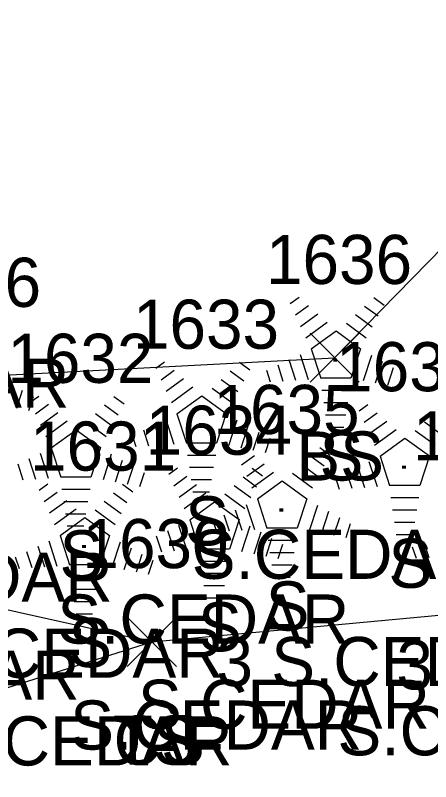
# Model space of a CAD drawing. Extents: x 1499292 to 1501024, y 534584 to 538043.
# Drawn here: x 1499918.42 to 1499935.33, y 537630.3 to 537661.49 of the extents above; entities that cross this region are included whole.
import ezdxf

# ---------------------------------------------------------------- set-up
doc = ezdxf.new("R2010")
doc.units = 0
for name, color, linetype in [('L_A', 7, 'Continuous'), ('L_C', 7, 'Continuous'), ('L_I', 7, 'Continuous'), ('L_TIC', 7, 'Continuous'), ('LELB', 7, 'Continuous'), ('LTC', 7, 'Continuous')]:
    doc.layers.add(name, color=color, linetype=linetype)

msp = doc.modelspace()

# ---------------------------------------------------------------- linework, layer by layer
at = {"layer": 'L_TIC'}
for points in [[(1499930.422, 537646.554), (1499932.422, 537648.554)], [(1499932.422, 537646.554), (1499930.422, 537648.554)], [(1499922.982, 537634.989), (1499924.982, 537636.989)], [(1499924.982, 537634.989), (1499922.982, 537636.989)], [(1499922.982, 537634.989), (1499924.982, 537636.989)], [(1499924.982, 537634.989), (1499922.982, 537636.989)]]:
    msp.add_lwpolyline(points, dxfattribs=at)
at = {"layer": 'LELB'}
for points in [[(1499846.934, 537679.187), (1499854.63, 537681.892), (1499855.345, 537682.192), (1499861.643, 537684.623), (1499869.851, 537675.621), (1499886.591, 537651.746), (1499898.304, 537639.55), (1499906.005, 537630.298), (1499923.982, 537635.989)], [(1499898.052, 537654.523), (1499915.347, 537646.709), (1499931.422, 537647.554), (1499937.751, 537654.019), (1499948.365, 537655.7)], [(1499898.052, 537654.523), (1499910.254, 537639.037), (1499923.982, 537635.989), (1499941.209, 537637.588), (1499959.262, 537638.094), (1499978.567, 537642.414), (1499993.025, 537642.588)]]:
    msp.add_lwpolyline(points, dxfattribs=at)
at = {"layer": 'LTC'}
for p, q in [((1499929.617, 537649.762), (1499929.972, 537650.02)), ((1499933.015, 537650.002), (1499933.434, 537649.698)), ((1499929.827, 537649.297), (1499930.356, 537649.681)), ((1499932.644, 537649.654), (1499933.194, 537649.255)), ((1499930.036, 537648.831), (1499930.74, 537649.342)), ((1499932.273, 537649.306), (1499932.952, 537648.812)), ((1499930.246, 537648.365), (1499931.124, 537649.003)), ((1499931.902, 537648.957), (1499932.712, 537648.369)), ((1499930.47, 537647.91), (1499931.482, 537648.645)), ((1499931.482, 537648.645), (1499932.479, 537647.92)), ((1499930.47, 537647.91), (1499930.857, 537646.717)), ((1499932.479, 537647.92), (1499932.088, 537646.717)), ((1499929.56, 537647.475), (1499929.832, 537646.639)), ((1499930.016, 537647.691), (1499930.347, 537646.672)), ((1499932.917, 537647.649), (1499932.579, 537646.609)), ((1499933.361, 537647.398), (1499933.074, 537646.514)), ((1499924.147, 537647.125), (1499924.501, 537647.383)), ((1499927.545, 537647.366), (1499927.964, 537647.061)), ((1499929.105, 537647.258), (1499929.317, 537646.606)), ((1499933.806, 537647.148), (1499933.569, 537646.419)), ((1499924.356, 537646.66), (1499924.886, 537647.044)), ((1499927.174, 537647.017), (1499927.723, 537646.618)), ((1499928.649, 537647.041), (1499928.802, 537646.573)), ((1499934.25, 537646.898), (1499934.063, 537646.324)), ((1499924.566, 537646.194), (1499925.27, 537646.705)), ((1499926.803, 537646.669), (1499927.482, 537646.175)), ((1499932.088, 537646.717), (1499930.857, 537646.717)), ((1499918.701, 537646.218), (1499918.464, 537645.488)), ((1499924.776, 537645.728), (1499925.654, 537646.366)), ((1499926.432, 537646.321), (1499927.241, 537645.732)), ((1499932.049, 537646.217), (1499930.905, 537646.217)), ((1499919.145, 537645.967), (1499918.959, 537645.393)), ((1499919.03, 537645.738), (1499919.385, 537645.995)), ((1499922.429, 537645.978), (1499922.848, 537645.674)), ((1499925, 537645.273), (1499926.012, 537646.008)), ((1499926.012, 537646.008), (1499927.009, 537645.283)), ((1499919.24, 537645.272), (1499919.769, 537645.657)), ((1499922.057, 537645.63), (1499922.607, 537645.231)), ((1499931.966, 537645.717), (1499930.977, 537645.717)), ((1499932.421, 537645.397), (1499932.775, 537645.654)), ((1499919.45, 537644.807), (1499920.153, 537645.318)), ((1499921.687, 537645.282), (1499922.366, 537644.788)), ((1499925, 537645.273), (1499925.387, 537644.08)), ((1499927.009, 537645.283), (1499926.618, 537644.08)), ((1499931.882, 537645.217), (1499931.05, 537645.217)), ((1499932.63, 537644.931), (1499933.16, 537645.316)), ((1499919.659, 537644.341), (1499920.537, 537644.979)), ((1499921.315, 537644.933), (1499922.125, 537644.345)), ((1499924.546, 537645.054), (1499924.876, 537644.035)), ((1499927.446, 537645.012), (1499927.108, 537643.972)), ((1499932.84, 537644.466), (1499933.544, 537644.977)), ((1499935.077, 537644.941), (1499935.756, 537644.447)), ((1499919.884, 537643.886), (1499920.895, 537644.62)), ((1499920.895, 537644.62), (1499921.892, 537643.895)), ((1499923.635, 537644.621), (1499923.846, 537643.969)), ((1499924.09, 537644.838), (1499924.361, 537644.002)), ((1499927.891, 537644.762), (1499927.603, 537643.877)), ((1499931.798, 537644.717), (1499931.123, 537644.717)), ((1499933.05, 537644), (1499933.928, 537644.638)), ((1499934.706, 537644.592), (1499935.515, 537644.004)), ((1499923.179, 537644.404), (1499923.331, 537643.937)), ((1499928.336, 537644.512), (1499928.098, 537643.782)), ((1499933.274, 537643.545), (1499934.286, 537644.279)), ((1499934.286, 537644.279), (1499935.283, 537643.554)), ((1499926.618, 537644.08), (1499925.387, 537644.08)), ((1499928.78, 537644.261), (1499928.593, 537643.687)), ((1499919.429, 537643.667), (1499919.76, 537642.647)), ((1499919.884, 537643.886), (1499920.271, 537642.692)), ((1499921.892, 537643.895), (1499921.501, 537642.692)), ((1499927.426, 537643.657), (1499927.78, 537643.914)), ((1499930.824, 537643.897), (1499931.243, 537643.593)), ((1499918.974, 537643.45), (1499919.245, 537642.615)), ((1499922.33, 537643.625), (1499921.992, 537642.585)), ((1499922.775, 537643.374), (1499922.487, 537642.49)), ((1499926.579, 537643.58), (1499925.435, 537643.58)), ((1499927.635, 537643.191), (1499928.164, 537643.576)), ((1499930.453, 537643.549), (1499931.002, 537643.15)), ((1499933.274, 537643.545), (1499933.661, 537642.351)), ((1499935.283, 537643.554), (1499934.892, 537642.351)), ((1499918.518, 537643.234), (1499918.73, 537642.582)), ((1499923.219, 537643.124), (1499922.982, 537642.395)), ((1499924.669, 537642.812), (1499925.024, 537643.069)), ((1499926.496, 537643.08), (1499925.507, 537643.08)), ((1499927.845, 537642.726), (1499928.548, 537643.237)), ((1499928.068, 537643.052), (1499928.487, 537642.748)), ((1499930.082, 537643.201), (1499930.761, 537642.707)), ((1499932.364, 537643.109), (1499932.635, 537642.274)), ((1499932.82, 537643.326), (1499933.15, 537642.306)), ((1499923.663, 537642.874), (1499923.477, 537642.3)), ((1499924.879, 537642.346), (1499925.408, 537642.73)), ((1499928.054, 537642.26), (1499928.933, 537642.898)), ((1499929.711, 537642.852), (1499930.52, 537642.263)), ((1499931.909, 537642.893), (1499932.12, 537642.241)), ((1499919.39, 537642.165), (1499919.744, 537642.423)), ((1499921.501, 537642.692), (1499920.271, 537642.692)), ((1499922.788, 537642.406), (1499923.207, 537642.101)), ((1499926.412, 537642.58), (1499925.58, 537642.58)), ((1499927.696, 537642.704), (1499928.246, 537642.305)), ((1499928.279, 537641.805), (1499929.291, 537642.539)), ((1499929.291, 537642.539), (1499930.288, 537641.814)), ((1499931.453, 537642.676), (1499931.605, 537642.208)), ((1499921.463, 537642.192), (1499920.318, 537642.192)), ((1499925.088, 537641.88), (1499925.792, 537642.392)), ((1499927.326, 537642.355), (1499928.005, 537641.862)), ((1499934.892, 537642.351), (1499933.661, 537642.351)), ((1499919.599, 537641.7), (1499920.129, 537642.084)), ((1499922.417, 537642.057), (1499922.966, 537641.658)), ((1499925.298, 537641.415), (1499926.176, 537642.053)), ((1499926.328, 537642.08), (1499925.653, 537642.08)), ((1499926.954, 537642.007), (1499927.764, 537641.418)), ((1499928.279, 537641.805), (1499928.666, 537640.611)), ((1499930.288, 537641.814), (1499929.896, 537640.611)), ((1499934.853, 537641.851), (1499933.709, 537641.851)), ((1499919.809, 537641.234), (1499920.513, 537641.745)), ((1499921.379, 537641.692), (1499920.391, 537641.692)), ((1499922.046, 537641.709), (1499922.725, 537641.215)), ((1499925.523, 537640.96), (1499926.534, 537641.694)), ((1499926.534, 537641.694), (1499927.531, 537640.969)), ((1499927.824, 537641.586), (1499928.155, 537640.566)), ((1499930.725, 537641.543), (1499930.387, 537640.504)), ((1499920.019, 537640.768), (1499920.897, 537641.406)), ((1499921.295, 537641.192), (1499920.464, 537641.192)), ((1499921.675, 537641.361), (1499922.484, 537640.772)), ((1499927.369, 537641.369), (1499927.64, 537640.534)), ((1499931.17, 537641.293), (1499930.882, 537640.408)), ((1499934.77, 537641.351), (1499933.781, 537641.351)), ((1499920.243, 537640.313), (1499921.255, 537641.048)), ((1499921.255, 537641.048), (1499922.252, 537640.323)), ((1499925.523, 537640.96), (1499925.91, 537639.766)), ((1499926.458, 537640.936), (1499926.61, 537640.468)), ((1499926.913, 537641.153), (1499927.125, 537640.501)), ((1499927.531, 537640.969), (1499927.14, 537639.766)), ((1499931.614, 537641.043), (1499931.377, 537640.313)), ((1499934.686, 537640.851), (1499933.854, 537640.851)), ((1499921.212, 537640.692), (1499920.537, 537640.692)), ((1499925.068, 537640.74), (1499925.399, 537639.721)), ((1499927.969, 537640.698), (1499927.631, 537639.659)), ((1499929.896, 537640.611), (1499928.666, 537640.611)), ((1499932.058, 537640.793), (1499931.872, 537640.218)), ((1499920.243, 537640.313), (1499920.63, 537639.12)), ((1499922.252, 537640.323), (1499921.861, 537639.12)), ((1499924.157, 537640.308), (1499924.369, 537639.656)), ((1499924.613, 537640.524), (1499924.884, 537639.689)), ((1499928.413, 537640.448), (1499928.126, 537639.563)), ((1499934.602, 537640.351), (1499933.927, 537640.351)), ((1499919.789, 537640.094), (1499920.119, 537639.075)), ((1499922.689, 537640.052), (1499922.351, 537639.012)), ((1499923.702, 537640.091), (1499923.854, 537639.623)), ((1499928.858, 537640.198), (1499928.621, 537639.468)), ((1499929.858, 537640.111), (1499928.713, 537640.111)), ((1499929.302, 537639.948), (1499929.116, 537639.373)), ((1499935.039, 537640.075), (1499935.251, 537639.424)), ((1499918.878, 537639.661), (1499919.089, 537639.009)), ((1499919.333, 537639.878), (1499919.604, 537639.042)), ((1499923.134, 537639.801), (1499922.846, 537638.917)), ((1499927.14, 537639.766), (1499925.91, 537639.766)), ((1499929.774, 537639.611), (1499928.786, 537639.611)), ((1499934.584, 537639.859), (1499934.736, 537639.391)), ((1499918.422, 537639.444), (1499918.574, 537638.976)), ((1499923.579, 537639.551), (1499923.341, 537638.822)), ((1499924.023, 537639.301), (1499923.836, 537638.727)), ((1499921.861, 537639.12), (1499920.63, 537639.12)), ((1499927.102, 537639.266), (1499925.957, 537639.266)), ((1499929.691, 537639.111), (1499928.859, 537639.111)), ((1499927.018, 537638.766), (1499926.03, 537638.766)), ((1499921.822, 537638.62), (1499920.678, 537638.62)), ((1499929.607, 537638.611), (1499928.932, 537638.611)), ((1499921.739, 537638.12), (1499920.75, 537638.12)), ((1499926.934, 537638.266), (1499926.103, 537638.266)), ((1499926.851, 537637.766), (1499926.176, 537637.766)), ((1499921.655, 537637.62), (1499920.823, 537637.62)), ((1499921.571, 537637.12), (1499920.896, 537637.12))]:
    msp.add_line(p, q, dxfattribs=at)

# ---------------------------------------------------------------- texts
at = {"layer": 'L_A'}
for s, p in [('BS', (1499929.863, 537642.554)), ('S', (1499930.808, 537642.554)), ('S', (1499925.337, 537639.917)), ('S', (1499920.221, 537638.53)), ('S', (1499933.611, 537638.189)), ('S', (1499928.616, 537636.449)), ('S', (1499925.86, 537635.604)), ('S', (1499920.58, 537634.957)), ('TS', (1499922.391, 537630.989)), ('CS', (1499922.423, 537630.989))]:
    msp.add_text(s, height=2, dxfattribs=at).set_placement(p)
at = {"layer": 'L_C'}
for s, p in [('S.CEDAR', (1499908.735, 537645.517)), ('S.CEDAR', (1499925.603, 537638.554)), ('S.CEDAR', (1499910.498, 537637.623)), ('S.CEDAR', (1499920.133, 537635.917)), ('S.CEDAR', (1499915.016, 537634.53)), ('3 S.CEDAR', (1499926.611, 537634.189)), ('3 S.CEDAR', (1499933.939, 537634.053)), ('S.CEDAR', (1499909.15, 537633.635)), ('S.CEDAR', (1499923.412, 537632.449)), ('S.CEDAR', (1499920.655, 537631.604)), ('S.CEDAR', (1499931.537, 537631.371)), ('S.CEDAR', (1499915.376, 537630.957))]:
    msp.add_text(s, height=2, dxfattribs=at).set_placement(p)
at = {"layer": 'L_I'}
for s, p in [('1636', (1499928.626, 537650.554)), ('1636', (1499928.626, 537650.554)), ('1626', (1499913.522, 537649.623)), ('1633', (1499923.211, 537647.917)), ('1632', (1499918.095, 537646.53)), ('1637', (1499931.485, 537646.189)), ('1635', (1499926.49, 537644.449)), ('1634', (1499923.734, 537643.604)), ('1638', (1499934.616, 537643.371)), ('1631', (1499919.021, 537642.957)), ('1630', (1499921.155, 537638.989)), ('1630', (1499921.155, 537638.989))]:
    msp.add_text(s, height=2, dxfattribs=at).set_placement(p)
at = {"layer": 'LTC'}
for p in [(1499931.364, 537647.658), (1499925.894, 537645.021), (1499920.778, 537643.634), (1499934.168, 537643.293), (1499929.173, 537641.553), (1499926.417, 537640.708), (1499921.137, 537640.061)]:
    msp.add_text('.', height=1.037, rotation=270, dxfattribs=at).set_placement(p)

doc.saveas('drawing.dxf')
